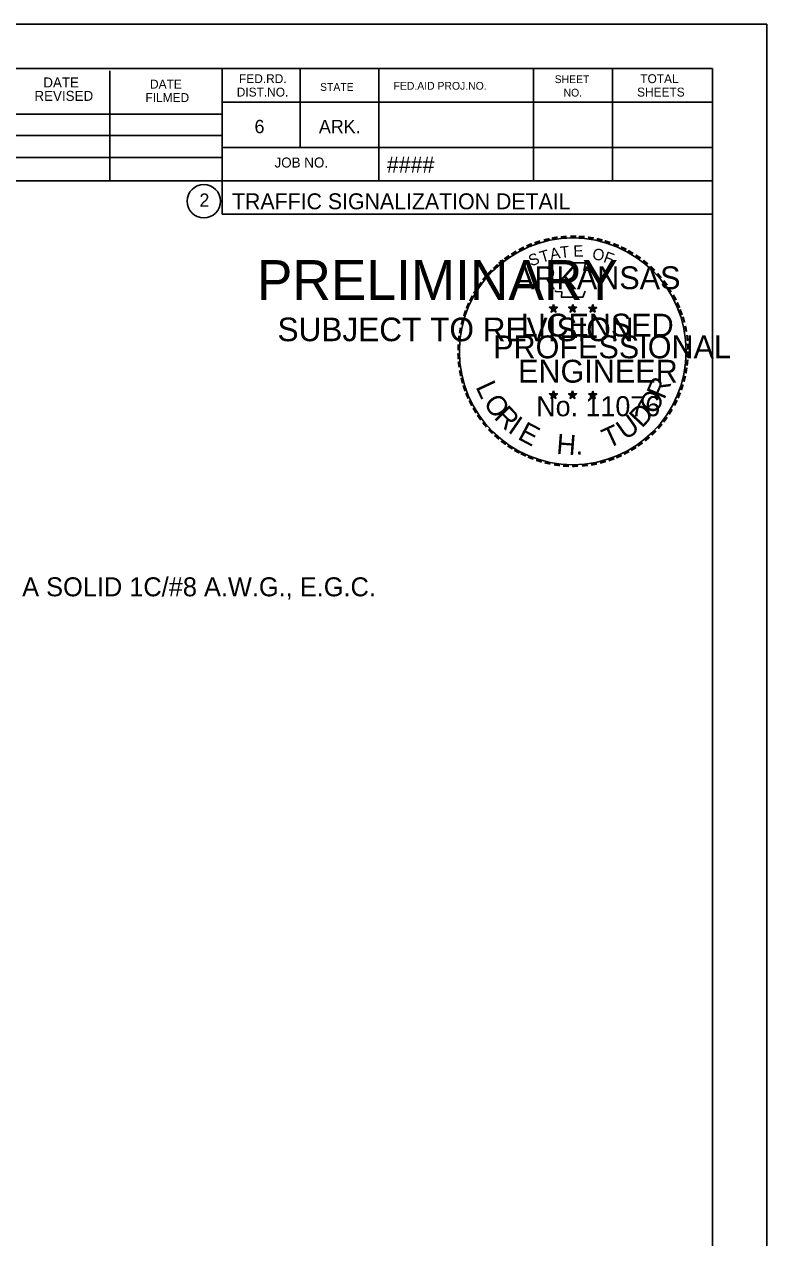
# Model space of a CAD drawing. Extents: x 1370140 to 1371141, y 380020 to 380660.
# Drawn here: x 1370944.8 to 1371140.5, y 380340 to 380660 of the extents above; entities that cross this region are included whole.
import ezdxf

# ---------------------------------------------------------------- set-up
doc = ezdxf.new("R2010")
doc.units = 0
for name, color, linetype in [('R_Border', 7, 'Continuous'), ('R_Border Notes', 7, 'Continuous'), ('R_Border Prem', 7, 'Continuous'), ('R_Draft', 7, 'Continuous'), ('R_No Plot', 7, 'Continuous')]:
    doc.layers.add(name, color=color, linetype=linetype)

msp = doc.modelspace()

# ---------------------------------------------------------------- linework, layer by layer
at = {"layer": 'R_Border'}
for p, q in [((1370177.71, 380648.36), (1371126.25, 380648.36)), ((1370967.37, 380618.72), (1370967.37, 380647.76)), ((1370996.95, 380648.36), (1370996.95, 380609.96)), ((1371017.47, 380648.36), (1371017.47, 380627.54)), ((1371038.29, 380648.36), (1371038.29, 380618.72)), ((1371079.03, 380648.36), (1371079.03, 380618.72)), ((1371099.85, 380648.36), (1371099.85, 380618.72)), ((1371126.25, 380031.98), (1371126.25, 380648.36)), ((1371126.25, 380639.54), (1370996.95, 380639.54)), ((1371126.25, 380639.6), (1371126.25, 380639.6)), ((1370879.47, 380636.3), (1370996.95, 380636.3)), ((1370879.47, 380630.72), (1370996.95, 380630.72)), ((1371126.25, 380627.54), (1370996.95, 380627.54)), ((1371005.83, 380627.54), (1371126.25, 380627.54)), ((1370879.47, 380624.9), (1370996.95, 380624.9)), ((1371126.25, 380618.72), (1370879.47, 380618.72)), ((1370996.95, 380609.96), (1371126.25, 380609.96))]:
    msp.add_line(p, q, dxfattribs=at)
msp.add_circle((1370992.11, 380613.36), 4.4, dxfattribs=at)
at = {"layer": 'R_Border Notes'}
for p, q in [((1371083.24, 380585.4), (1371084.3, 380585.06)), ((1371083.24, 380585.4), (1371084.02, 380585.28)), ((1371083.24, 380585.4), (1371083.95, 380585.03)), ((1371083.64, 380584.16), (1371084.3, 380585.06)), ((1371083.64, 380584.16), (1371084.02, 380584.91)), ((1371083.64, 380584.16), (1371084.26, 380584.82)), ((1371084.3, 380586.18), (1371084.17, 380585.4)), ((1371084.95, 380584.16), (1371084.26, 380584.82)), ((1371084.3, 380585.06), (1371084.3, 380586.18)), ((1371084.3, 380586.18), (1371084.45, 380585.44)), ((1371085.32, 380585.4), (1371084.3, 380585.06)), ((1371084.95, 380584.16), (1371084.3, 380585.06)), ((1371085.32, 380585.4), (1371084.48, 380585.25)), ((1371084.95, 380584.16), (1371084.51, 380585.03)), ((1371085.32, 380585.4), (1371084.73, 380585.09)), ((1371088.29, 380585.4), (1371089.35, 380585.06)), ((1371088.29, 380585.4), (1371089.04, 380585.28)), ((1371088.29, 380585.4), (1371088.98, 380585.03)), ((1371088.67, 380584.16), (1371089.35, 380585.06)), ((1371088.67, 380584.16), (1371089.07, 380584.91)), ((1371088.67, 380584.16), (1371089.32, 380584.82)), ((1371089.35, 380586.18), (1371089.22, 380585.4)), ((1371089.97, 380584.16), (1371089.32, 380584.82)), ((1371089.35, 380585.06), (1371089.35, 380586.18)), ((1371089.35, 380586.18), (1371089.47, 380585.44)), ((1371090.37, 380585.4), (1371089.35, 380585.06)), ((1371089.97, 380584.16), (1371089.35, 380585.06)), ((1371090.37, 380585.4), (1371089.5, 380585.25)), ((1371089.97, 380584.16), (1371089.53, 380585.03)), ((1371090.37, 380585.4), (1371089.75, 380585.09)), ((1371093.6, 380585.37), (1371094.65, 380585.03)), ((1371093.6, 380585.37), (1371094.34, 380585.22)), ((1371093.6, 380585.37), (1371094.31, 380585)), ((1371093.97, 380584.13), (1371094.65, 380585.03)), ((1371093.97, 380584.13), (1371094.37, 380584.88)), ((1371093.97, 380584.13), (1371094.65, 380584.78)), ((1371094.65, 380586.12), (1371094.53, 380585.37)), ((1371094.65, 380585.03), (1371094.65, 380586.12)), ((1371094.65, 380586.12), (1371094.77, 380585.37)), ((1371095.7, 380585.37), (1371094.65, 380585.03)), ((1371095.27, 380584.13), (1371094.65, 380585.03)), ((1371095.27, 380584.13), (1371094.65, 380584.78)), ((1371095.7, 380585.37), (1371094.8, 380585.22)), ((1371095.27, 380584.13), (1371094.87, 380585)), ((1371095.7, 380585.37), (1371095.05, 380585.06)), ((1371083.21, 380562.59), (1371084.26, 380562.25)), ((1371083.21, 380562.59), (1371084.02, 380562.43)), ((1371083.21, 380562.59), (1371083.95, 380562.22)), ((1371083.64, 380561.35), (1371084.26, 380562.25)), ((1371083.64, 380561.35), (1371084.02, 380562.09)), ((1371083.64, 380561.35), (1371084.26, 380562.03)), ((1371084.26, 380563.33), (1371084.14, 380562.59)), ((1371084.26, 380562.25), (1371084.26, 380563.33)), ((1371084.26, 380563.33), (1371084.42, 380562.59)), ((1371085.32, 380562.59), (1371084.26, 380562.25)), ((1371084.95, 380561.35), (1371084.26, 380562.25)), ((1371084.95, 380561.35), (1371084.26, 380562)), ((1371085.32, 380562.59), (1371084.45, 380562.43)), ((1371084.95, 380561.35), (1371084.51, 380562.22)), ((1371085.32, 380562.59), (1371084.73, 380562.28)), ((1371088.26, 380562.59), (1371089.32, 380562.25)), ((1371088.26, 380562.59), (1371089.04, 380562.43)), ((1371088.26, 380562.59), (1371088.98, 380562.22)), ((1371088.67, 380561.35), (1371089.32, 380562.25)), ((1371088.67, 380561.35), (1371089.04, 380562.09)), ((1371088.67, 380561.35), (1371089.32, 380562.03)), ((1371089.32, 380563.33), (1371089.19, 380562.59)), ((1371089.32, 380562.25), (1371089.32, 380563.33)), ((1371089.32, 380563.33), (1371089.44, 380562.59)), ((1371090.37, 380562.59), (1371089.32, 380562.25)), ((1371089.94, 380561.35), (1371089.32, 380562.25)), ((1371089.94, 380561.35), (1371089.32, 380562)), ((1371090.37, 380562.59), (1371089.47, 380562.43)), ((1371089.94, 380561.35), (1371089.53, 380562.22)), ((1371090.37, 380562.59), (1371089.72, 380562.28)), ((1371093.6, 380562.56), (1371094.65, 380562.22)), ((1371093.6, 380562.56), (1371094.34, 380562.4)), ((1371093.6, 380562.56), (1371094.31, 380562.19)), ((1371093.97, 380561.32), (1371094.65, 380562.22)), ((1371093.97, 380561.32), (1371094.37, 380562.06)), ((1371093.97, 380561.32), (1371094.65, 380562)), ((1371094.65, 380563.3), (1371094.53, 380562.56)), ((1371094.65, 380562.22), (1371094.65, 380563.3)), ((1371094.65, 380563.3), (1371094.77, 380562.56)), ((1371095.7, 380562.56), (1371094.65, 380562.22)), ((1371095.27, 380561.32), (1371094.65, 380562.22)), ((1371095.27, 380561.32), (1371094.65, 380561.97)), ((1371095.7, 380562.56), (1371094.8, 380562.4)), ((1371095.27, 380561.32), (1371094.84, 380562.19)), ((1371095.7, 380562.56), (1371095.05, 380562.25))]:
    msp.add_line(p, q, dxfattribs=at)
for points in [[(1371083.37, 380597.09), (1371084.17, 380594.58)], [(1371093.94, 380594.33), (1371094.37, 380595.17), (1371092.32, 380595.11), (1371092.73, 380597.09), (1371083.37, 380597.09)], [(1371084.85, 380589.81), (1371084.85, 380589.53), (1371086.53, 380589.47), (1371086.37, 380588.04), (1371092.01, 380588.04), (1371092.63, 380589.65)], [(1371084.3, 380586.18), (1371084.95, 380584.16), (1371083.24, 380585.4), (1371085.32, 380585.4), (1371083.64, 380584.16), (1371084.3, 380586.18)], [(1371089.35, 380586.18), (1371089.97, 380584.16), (1371088.29, 380585.4), (1371090.37, 380585.4), (1371088.67, 380584.16), (1371089.35, 380586.18)], [(1371094.65, 380586.12), (1371095.27, 380584.13), (1371093.6, 380585.37), (1371095.7, 380585.37), (1371093.97, 380584.13), (1371094.65, 380586.12)], [(1371084.26, 380563.33), (1371084.95, 380561.35), (1371083.21, 380562.59), (1371085.32, 380562.59), (1371083.64, 380561.35), (1371084.26, 380563.33)], [(1371089.32, 380563.33), (1371089.94, 380561.35), (1371088.26, 380562.59), (1371090.37, 380562.59), (1371088.67, 380561.35), (1371089.32, 380563.33)], [(1371094.65, 380563.3), (1371095.27, 380561.32), (1371093.6, 380562.56), (1371095.7, 380562.56), (1371093.97, 380561.32), (1371094.65, 380563.3)]]:
    msp.add_lwpolyline(points, dxfattribs=at)
for centre, radius in [((1371089.39, 380573.78), 29.9), ((1371084.27, 380585.06), 0.519), ((1371084.27, 380585.06), 0.436), ((1371084.27, 380585.06), 0.349), ((1371084.27, 380585.06), 0.299), ((1371084.27, 380585.06), 0.225), ((1371084.27, 380585.06), 0.149), ((1371084.27, 380585.06), 0.0893), ((1371089.3, 380585.06), 0.519), ((1371089.3, 380585.06), 0.436), ((1371089.3, 380585.06), 0.349), ((1371089.3, 380585.06), 0.299), ((1371089.3, 380585.06), 0.225), ((1371089.3, 380585.06), 0.149), ((1371089.3, 380585.06), 0.0893), ((1371094.61, 380585.02), 0.519), ((1371094.61, 380585.02), 0.436), ((1371094.61, 380585.02), 0.349), ((1371094.61, 380585.02), 0.299), ((1371094.61, 380585.02), 0.225), ((1371094.61, 380585.02), 0.149), ((1371094.61, 380585.02), 0.0893), ((1371084.26, 380562.24), 0.519), ((1371084.26, 380562.24), 0.436), ((1371084.26, 380562.24), 0.349), ((1371084.26, 380562.24), 0.299), ((1371084.26, 380562.24), 0.225), ((1371084.26, 380562.24), 0.149), ((1371084.26, 380562.24), 0.0893), ((1371089.28, 380562.24), 0.519), ((1371089.28, 380562.24), 0.436), ((1371089.28, 380562.24), 0.349), ((1371089.28, 380562.24), 0.299), ((1371089.28, 380562.24), 0.225), ((1371089.28, 380562.24), 0.149), ((1371089.28, 380562.24), 0.0893), ((1371094.61, 380562.21), 0.519), ((1371094.61, 380562.21), 0.436), ((1371094.61, 380562.21), 0.349), ((1371094.61, 380562.21), 0.299), ((1371094.61, 380562.21), 0.225), ((1371094.61, 380562.21), 0.149), ((1371094.61, 380562.21), 0.0893)]:
    msp.add_circle(centre, radius, dxfattribs=at)
at = {"layer": 'R_No Plot'}
msp.add_line((1370140.51, 380660.04), (1371140.51, 380660.04), dxfattribs=at)
msp.add_lwpolyline([(1370140.49, 380660.04), (1371140.51, 380660.04), (1371140.51, 380020.03), (1370140.49, 380020.03)], close=True, dxfattribs=at)

# ---------------------------------------------------------------- texts
at = {"layer": 'R_Border'}
for s, height, p in [('DATE', 2.638, (1370949.79, 380643.38)), ('DATE', 2.346, (1370977.93, 380643.08)), ('FED.RD.', 2.346, (1371001.39, 380644.52)), ('STATE', 2.052, (1371022.75, 380642.48)), ('FED.AID PROJ.NO.', 2.052, (1371042.13, 380642.78)), ('SHEET', 2.052, (1371084.61, 380644.52)), ('TOTAL', 2.346, (1371107.17, 380644.52)), ('REVISED', 2.638, (1370947.45, 380639.84)), ('FILMED', 2.346, (1370976.73, 380639.54)), ('DIST.NO.', 2.346, (1371000.79, 380640.98)), ('NO.', 2.052, (1371086.95, 380640.98)), ('SHEETS', 2.346, (1371106.33, 380640.98)), ('6', 3.52, (1371005.47, 380631.32)), ('ARK.', 3.517, (1371022.45, 380631.32)), ('JOB NO.', 2.638, (1371010.75, 380622.26)), ('####', 4.2, (1371040.38, 380620.93)), ('2', 3.52, (1370990.96, 380611.9)), ('TRAFFIC SIGNALIZATION DETAIL ', 4.2, (1370999.54, 380611.25))]:
    msp.add_text(s, height=height, dxfattribs=at).set_placement(p)
at = {"layer": 'R_Border Notes'}
for s, height, rotation, p in [('-', 4.82, 19.1761, (1371079.61, 380600.5)), ('-', 4.82, 13.6301, (1371081.88, 380601.21)), ('-', 4.82, 10.2193, (1371083.89, 380601.71)), ('-', 4.82, 5.8968, (1371086.09, 380602.02)), ('-', 4.82, 0.1862, (1371088.42, 380602.24)), ('-', 4.82, 357.743, (1371090.59, 380602.21)), ('-', 4.82, 352.1617, (1371092.82, 380602.02)), ('-', 4.82, 347.2049, (1371094.99, 380601.71)), ('-', 4.82, 342.3362, (1371096.94, 380601.21)), ('-', 4.82, 34.0636, (1371073.97, 380597.62)), ('-', 4.82, 28.7918, (1371075.77, 380598.73)), ('-', 4.82, 24.3072, (1371077.66, 380599.7)), ('S', 3.01, 21.594, (1371078.41, 380596.13)), ('T', 3.01, 16.4036, (1371081.16, 380597.12)), ('A', 3.01, 11.2132, (1371083.64, 380597.87)), ('T', 3.01, 6.0228, (1371086.19, 380598.39)), ('E', 3.01, 0.8323, (1371089.53, 380598.73)), ('O', 3.01, 350.4515, (1371094.37, 380598.08)), ('F', 3.01, 340.0707, (1371097.25, 380597.4)), ('-', 4.82, 337.8551, (1371099.11, 380600.56)), ('-', 4.82, 334.1211, (1371101.04, 380599.76)), ('-', 4.82, 329.6409, (1371102.77, 380598.89)), ('-', 4.82, 42.9622, (1371069.51, 380594.02)), ('-', 4.82, 38.9507, (1371070.81, 380595.29)), ('-', 4.82, 36.2317, (1371072.21, 380596.44)), ('-', 4.82, 325.8627, (1371104.69, 380597.8)), ('-', 4.82, 320.5297, (1371106.55, 380596.53)), ('-', 4.82, 50.6142, (1371066.9, 380591.14)), ('-', 4.82, 48.4231, (1371068.14, 380592.57)), ('-', 4.82, 315.5786, (1371108.35, 380595.05)), ('-', 4.82, 309.8797, (1371110.06, 380593.37)), ('-', 4.82, 58.0706, (1371064.7, 380587.82)), ('-', 4.82, 54.2325, (1371065.7, 380589.4)), ('-', 4.82, 306.6522, (1371111.67, 380591.57)), ('-', 4.22, 303.6753, (1371113.09, 380589.87)), ('-', 4.82, 62.8713, (1371063.74, 380585.96)), ('-', 4.82, 299.6684, (1371114.09, 380588.01)), ('-', 4.82, 72.3945, (1371062.35, 380582.24)), ('-', 4.82, 67.7743, (1371062.97, 380584.13)), ('-', 4.82, 294.6628, (1371115.08, 380586.18)), ('-', 4.82, 290.5728, (1371115.82, 380584.47)), ('-', 4.82, 75.461, (1371061.73, 380580.07)), ('-', 4.82, 285.1233, (1371116.54, 380582.71)), ('-', 4.82, 280.5493, (1371117.16, 380580.44)), ('-', 4.82, 85.1863, (1371061.11, 380575.86)), ('-', 4.82, 81.2013, (1371061.36, 380577.93)), ('-', 4.82, 276.5962, (1371117.62, 380578.18)), ('-', 4.82, 89.0622, (1371061.05, 380573.75)), ('-', 4.82, 274.3301, (1371117.81, 380575.98)), ('-', 4.82, 94.1959, (1371061.14, 380571.55)), ('-', 4.82, 98.9479, (1371061.36, 380569.56)), ('-', 4.82, 263.5172, (1371117.84, 380572.07)), ('-', 4.82, 269.9407, (1371117.9, 380574.06)), ('-', 4.82, 101.7149, (1371061.76, 380567.33)), ('-', 4.82, 260.9953, (1371117.62, 380570.09)), ('-', 4.82, 105.4578, (1371062.25, 380565.53)), ('-', 4.82, 109.0874, (1371062.87, 380563.64)), ('L', 5.29, 294.8545, (1371063.68, 380564.44)), ('R', 5.29, 66.7131, (1371113.5, 380560.87)), ('-', 4.82, 252.8681, (1371116.75, 380565.87)), ('-', 4.82, 255.7626, (1371117.31, 380568.04)), ('-', 4.82, 114.0643, (1371063.65, 380561.84)), ('O', 5.29, 304.6604, (1371065.65, 380560.2)), ('O', 5.29, 56.5567, (1371110.84, 380556.82)), ('-', 4.82, 247.8887, (1371116.1, 380563.86)), ('-', 4.82, 115.7289, (1371064.58, 380559.98)), ('-', 4.82, 120.4471, (1371065.66, 380558.22)), ('R', 5.29, 314.8169, (1371068.41, 380556.23)), ('D', 5.29, 46.5755, (1371107.58, 380553.36)), ('-', 4.82, 239.0712, (1371114.12, 380559.71)), ('-', 4.82, 244.6197, (1371115.3, 380561.97)), ('-', 4.82, 125.8934, (1371066.84, 380556.54)), ('-', 4.82, 130.7181, (1371068.27, 380554.84)), ('I', 5.29, 325.4992, (1371072.03, 380552.64)), ('E', 5.29, 332.15, (1371074.6, 380550.78)), ('U', 5.29, 35.3674, (1371103.26, 380550.21)), ('-', 4.82, 233.8452, (1371112.91, 380557.75)), ('-', 4.82, 134.2238, (1371069.82, 380553.23)), ('-', 4.82, 138.9338, (1371071.4, 380551.83)), ('H', 5.29, 355.5303, (1371084.94, 380546.8)), ('T', 5.29, 24.6851, (1371098.65, 380548.05)), ('-', 4.82, 225.7653, (1371110.15, 380554.34)), ('-', 4.82, 231.2538, (1371111.61, 380556.02)), ('-', 4.82, 144.6463, (1371073.07, 380550.59)), ('-', 4.82, 148.0898, (1371074.75, 380549.48)), ('-', 4.82, 212.2491, (1371105.34, 380550.22)), ('-', 4.82, 215.7363, (1371106.93, 380551.4)), ('-', 4.82, 221.0851, (1371108.6, 380552.79)), ('-', 4.82, 151.5704, (1371076.48, 380548.48)), ('-', 4.82, 154.6002, (1371078.1, 380547.77)), ('-', 4.82, 158.5612, (1371079.96, 380547)), ('-', 4.82, 162.7983, (1371082.03, 380546.34)), ('.', 5.29, 6.5632, (1371090.19, 380546.44)), ('-', 4.82, 200.7184, (1371099.92, 380547.37)), ('-', 4.82, 204.2516, (1371101.78, 380548.17)), ('-', 4.82, 207.3568, (1371103.64, 380549.17)), ('-', 4.82, 167.5555, (1371084.17, 380545.88)), ('-', 4.82, 173.1155, (1371086.5, 380545.54)), ('-', 4.82, 176.5183, (1371088.76, 380545.35)), ('-', 4.82, 181.5918, (1371091.02, 380545.41)), ('-', 4.82, 185.8167, (1371093.44, 380545.66)), ('-', 4.82, 191.2858, (1371095.67, 380546.03)), ('-', 4.82, 195.4743, (1371097.87, 380546.65))]:
    msp.add_text(s, height=height, rotation=rotation, dxfattribs=at).set_placement(p)
for s, height, p in [('ARKANSAS', 6.026, (1371073.88, 380590.18)), ('LICENSED', 6.026, (1371075.68, 380577.69)), ('PROFESSIONAL', 6.0264, (1371068.39, 380571.95)), ('ENGINEER', 6.026, (1371074.96, 380565.53)), ('No. 11076', 5.294, (1371079.75, 380556.67))]:
    msp.add_text(s, height=height, dxfattribs=at).set_placement(p)
at = {"layer": 'R_Border Prem'}
for s, height, p in [('PRELIMINARY', 10.5, (1371006.1, 380587.35)), ('SUBJECT TO REVISION', 6.2253, (1371011.53, 380576.46))]:
    msp.add_text(s, height=height, dxfattribs=at).set_placement(p)
at = {"layer": 'R_Draft'}
msp.add_text(' 1/2" NMC WITH A SOLID 1C/#8 A.W.G., E.G.C.', height=5, dxfattribs=at).set_placement((1370892.81, 380509.19))

doc.saveas('drawing.dxf')
